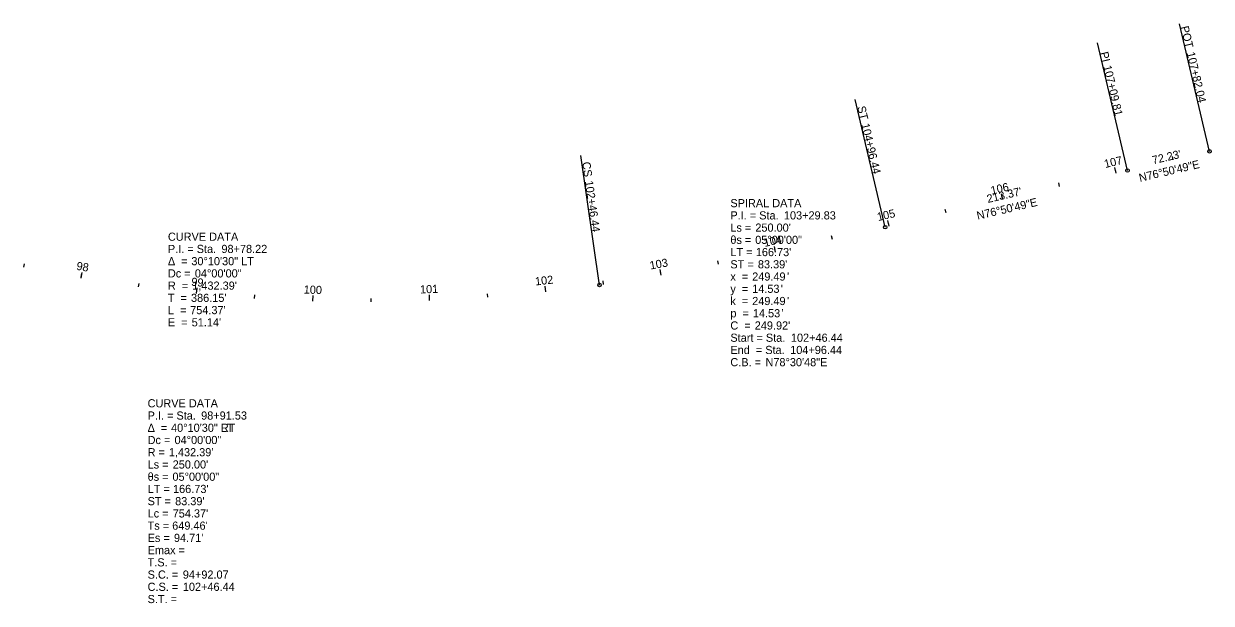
# Model space of a CAD drawing. Extents: x 1999328 to 2003366, y 252318 to 253988.
# Drawn here: x 2002348 to 2003366, y 252507 to 253005 of the extents above; entities that cross this region are included whole.
import ezdxf

# ---------------------------------------------------------------- set-up
doc = ezdxf.new("R2010")
doc.units = 0
for name, color, linetype in [('GE_P_Alignment_500_Stations', 7, 'Continuous'), ('GE_X_Alignment_100_Stations', 7, 'Continuous'), ('SC_Scratch3', 7, 'Continuous'), ('SV_X_Mon_Cells_Found', 7, 'Continuous'), ('TX_P_50', 7, 'Continuous'), ('TX_X_50', 7, 'Continuous')]:
    doc.layers.add(name, color=color, linetype=linetype)

msp = doc.modelspace()

# ---------------------------------------------------------------- linework, layer by layer
at = {"layer": 'GE_P_Alignment_500_Stations'}
for p, q in [((2003364.9, 252895.3), (2003339.3, 253004.9)), ((2003294.6, 252878.9), (2003269, 252988.4)), ((2003086.8, 252830.3), (2003061.2, 252939.9)), ((2002841.9, 252780.6), (2002826, 252891.9)), ((2003333.7, 252888), (2003333.1, 252891)), ((2003285, 252876.7), (2003283.9, 252881.5)), ((2003236.4, 252865.3), (2003235.7, 252868.2)), ((2003187.7, 252853.9), (2003186.5, 252858.8)), ((2003139, 252842.5), (2003138.3, 252845.5)), ((2003090.3, 252831.2), (2003089.2, 252836)), ((2003041.6, 252819.8), (2003040.9, 252822.7)), ((2002992.8, 252808.8), (2002991.8, 252813.7)), ((2002348.2, 252795.9), (2002348.8, 252798.8)), ((2002943.9, 252798.5), (2002943.3, 252801.4)), ((2002397.3, 252786.6), (2002398.2, 252791.5)), ((2002894.8, 252789.1), (2002893.9, 252794)), ((2002446.7, 252779), (2002447.1, 252782)), ((2002496.4, 252773.2), (2002496.9, 252778.2)), ((2002795.9, 252774.7), (2002795.3, 252779.7)), ((2002845.4, 252781.1), (2002845, 252784.1)), ((2002546.2, 252769.1), (2002546.4, 252772.1)), ((2002596.2, 252766.7), (2002596.3, 252771.7)), ((2002646.2, 252766.1), (2002646.2, 252769.1)), ((2002696.2, 252767.3), (2002696, 252772.2)), ((2002746.1, 252770.1), (2002745.8, 252773.1))]:
    msp.add_line(p, q, dxfattribs=at)
for centre in [(2003364.9, 252895.3), (2003294.6, 252878.9), (2003086.8, 252830.3), (2002841.9, 252780.6)]:
    msp.add_circle(centre, 1.5, dxfattribs=at)
at = {"layer": 'SV_X_Mon_Cells_Found'}
for p, q in [((2003364.9, 252895.3), (2003339.3, 253004.9)), ((2003294.6, 252878.9), (2003269, 252988.4)), ((2003086.8, 252830.3), (2003061.2, 252939.9)), ((2002841.9, 252780.6), (2002826, 252891.9)), ((2003090.3, 252831.2), (2003089.6, 252834.1)), ((2002596.2, 252766.7), (2002596.3, 252771.7))]:
    msp.add_line(p, q, dxfattribs=at)
for centre in [(2003364.9, 252895.3), (2003294.6, 252878.9), (2003086.8, 252830.3), (2002841.9, 252780.6)]:
    msp.add_circle(centre, 1.5, dxfattribs=at)
at = {"layer": 'TX_P_50'}
for p, q in [((2003364.9, 252895.3), (2003339.3, 253004.9)), ((2003294.6, 252878.9), (2003269, 252988.4)), ((2003086.8, 252830.3), (2003061.2, 252939.9)), ((2002841.9, 252780.6), (2002826, 252891.9)), ((2003285, 252876.7), (2003284.4, 252879.6)), ((2003187.7, 252853.9), (2003187, 252856.8)), ((2003090.3, 252831.2), (2003089.2, 252836)), ((2002992.8, 252808.8), (2002992.2, 252811.7)), ((2002397.3, 252786.6), (2002397.8, 252789.6)), ((2002894.8, 252789.1), (2002894.3, 252792)), ((2002496.4, 252773.2), (2002496.7, 252776.2)), ((2002596.2, 252766.7), (2002596.3, 252771.7)), ((2002696.2, 252767.3), (2002696, 252770.2)), ((2002795.9, 252774.7), (2002795.5, 252777.7))]:
    msp.add_line(p, q, dxfattribs=at)
for centre in [(2003364.9, 252895.3), (2003294.6, 252878.9), (2003086.8, 252830.3), (2002841.9, 252780.6)]:
    msp.add_circle(centre, 1.5, dxfattribs=at)

# ---------------------------------------------------------------- texts
at = {"layer": 'GE_P_Alignment_500_Stations'}
for s, rotation, p in [('POT', 283.1531, (2003340.1, 253002.1)), ('PI', 283.1531, (2003271.1, 252980)), ('107+82.04', 283.1531, (2003345.3, 252979.9)), ('107+09.81', 283.1531, (2003273.8, 252968.4)), ('ST', 283.1531, (2003062.9, 252933.4)), ('104+96.44', 283.1531, (2003066.3, 252918.6)), ('107', 13.1531, (2003275.5, 252881)), ("72.23'", 13.1531, (2003316.6, 252884.2)), ('CS', 278.1531, (2002827, 252885.9)), ('N76°50\'49"E', 13.1531, (2003305.3, 252869.1)), ('102+46.44', 278.1531, (2002829.3, 252869.7)), ("213.37'", 13.1531, (2003174.9, 252851)), ('106', 13.1531, (2003178.2, 252858.2)), ('N76°50\'49"E', 13.1531, (2003166.2, 252836.6)), ('105', 13.1531, (2003080.8, 252835.5)), ('104', 12.4091, (2002983.6, 252813.3)), ('98', 350.2955, (2002393, 252793.8)), ('103', 10.066, (2002885.6, 252793.9)), ('102', 6.2955, (2002787, 252780.2)), ('99', 354.2955, (2002491.6, 252780.1)), ('100', 358.2955, (2002588.2, 252773.3)), ('101', 2.2955, (2002688.1, 252773.3))]:
    msp.add_text(s, height=7, rotation=rotation, dxfattribs=at).set_placement(p)
at = {"layer": 'GE_X_Alignment_100_Stations'}
for s, p in [('SPIRAL DATA', (2002954.1, 252847.4)), ('P.I. = Sta. ', (2002954.1, 252836.9)), ('103+29.83', (2003000, 252836.9)), ('Ls = ', (2002954.1, 252826.4)), ("250.00'", (2002975.5, 252826.4)), ('CURVE DATA', (2002471.8, 252818.6)), ('θs = ', (2002954.1, 252815.9)), ('05°00\'00"', (2002975.4, 252815.9)), ('P.I. = Sta. ', (2002471.8, 252808.1)), ('98+78.22', (2002517.7, 252808.1)), ('LT = ', (2002954.1, 252805.4)), ("166.73'", (2002975.9, 252805.4)), ('Δ  = ', (2002471.8, 252797.6)), ('30°10\'30" LT', (2002491.9, 252797.6)), ('ST = ', (2002954.1, 252794.9)), ("83.39'", (2002977.7, 252794.9)), ('Dc = ', (2002471.8, 252787.1)), ('04°00\'00"', (2002494.9, 252787.1)), ('x  = ', (2002954.1, 252784.4)), ('249.49', (2002972.8, 252784.4)), ("'", (2003002.7, 252784.4)), ('R  = ', (2002471.8, 252776.6)), ("1,432.39'", (2002492.7, 252776.6)), ('y  = ', (2002954.1, 252773.9)), ('14.53', (2002972.8, 252773.9)), ("'", (2002997.3, 252773.9)), ('T  = ', (2002471.8, 252766.1)), ("386.15'", (2002491.6, 252766.1)), ('k  = ', (2002954.1, 252763.4)), ('249.49', (2002972.8, 252763.4)), ("'", (2003002.7, 252763.4)), ('L  = ', (2002471.8, 252755.6)), ("754.37'", (2002490.9, 252755.6)), ('p  = ', (2002954.1, 252752.9)), ('14.53', (2002973.4, 252752.9)), ("'", (2002997.8, 252752.9)), ('E  = ', (2002471.8, 252745.1)), ("51.14'", (2002492.2, 252745.1)), ('C  = ', (2002954.1, 252742.4)), ("249.92'", (2002975, 252742.4)), ('Start = Sta. ', (2002954.1, 252731.9)), ('102+46.44', (2003006, 252731.9)), ('End  = Sta. ', (2002954.1, 252721.4)), ('104+96.44', (2003005.4, 252721.4)), ('C.B. = ', (2002954.1, 252710.9)), ('N78°30\'48"E', (2002984.2, 252710.9)), ('CURVE DATA', (2002454.4, 252675.6)), ('CURVE DATA', (2002454.4, 252675.6)), ('P.I. = Sta. ', (2002454.4, 252665.1)), ('P.I. = Sta. ', (2002454.4, 252665.1)), ('98+91.53', (2002500.3, 252665.1)), ('98+91.53', (2002500.3, 252665.1)), ('Δ  = ', (2002454.4, 252654.6)), ('Δ  = ', (2002454.4, 252654.6)), ('40°10\'30" LT', (2002474.5, 252654.6)), ('40°10\'30" RT', (2002474.5, 252654.6)), ('Dc = ', (2002454.4, 252644.1)), ('Dc = ', (2002454.4, 252644.1)), ('04°00\'00"', (2002477.5, 252644.1)), ('04°00\'00"', (2002477.5, 252644.1)), ('R = ', (2002454.4, 252633.6)), ('R = ', (2002454.4, 252633.6)), ("1,432.39'", (2002472.6, 252633.6)), ("1,432.39'", (2002472.6, 252633.6)), ('Ls = ', (2002454.4, 252623.1)), ('Ls = ', (2002454.4, 252623.1)), ("250.00'", (2002475.9, 252623.1)), ("250.00'", (2002475.9, 252623.1)), ('θs = ', (2002454.4, 252612.6)), ('θs = ', (2002454.4, 252612.6)), ('05°00\'00"', (2002475.7, 252612.6)), ('05°00\'00"', (2002475.7, 252612.6)), ('LT = ', (2002454.4, 252602.1)), ('LT = ', (2002454.4, 252602.1)), ("166.73'", (2002476.2, 252602.1)), ("166.73'", (2002476.2, 252602.1)), ('ST = ', (2002454.4, 252591.6)), ('ST = ', (2002454.4, 252591.6)), ("83.39'", (2002478, 252591.6)), ("83.39'", (2002478, 252591.6)), ('Lc = ', (2002454.4, 252581.1)), ('Lc = ', (2002454.4, 252581.1)), ("754.37'", (2002475.9, 252581.1)), ("754.37'", (2002475.9, 252581.1)), ('Ts = ', (2002454.4, 252570.6)), ('Ts = ', (2002454.4, 252570.6)), ("649.46'", (2002475.5, 252570.6)), ("649.46'", (2002475.5, 252570.6)), ('Es = ', (2002454.4, 252560.1)), ('Es = ', (2002454.4, 252560.1)), ("94.71'", (2002477, 252560.1)), ("94.71'", (2002477, 252560.1)), ('Emax = ', (2002454.4, 252549.6)), ('Emax = ', (2002454.4, 252549.6)), ('T.S. = ', (2002454.4, 252539.1)), ('T.S. = ', (2002454.4, 252539.1)), ('S.C. = ', (2002454.4, 252528.6)), ('S.C. = ', (2002454.4, 252528.6)), ('94+92.07', (2002484.6, 252528.6)), ('94+92.07', (2002484.6, 252528.6)), ('C.S. = ', (2002454.4, 252518.1)), ('C.S. = ', (2002454.4, 252518.1)), ('102+46.44', (2002484.6, 252518.1)), ('102+46.44', (2002484.6, 252518.1)), ('S.T. = ', (2002454.4, 252507.6)), ('S.T. = ', (2002454.4, 252507.6))]:
    msp.add_text(s, height=7, dxfattribs=at).set_placement(p)
at = {"layer": 'SC_Scratch3'}
for s, p in [('SPIRAL DATA', (2002954.1, 252847.4)), ('P.I. = Sta. ', (2002954.1, 252836.9)), ('103+29.83', (2003000, 252836.9)), ('Ls = ', (2002954.1, 252826.4)), ("250.00'", (2002975.5, 252826.4)), ('CURVE DATA', (2002471.8, 252818.6)), ('θs = ', (2002954.1, 252815.9)), ('05°00\'00"', (2002975.4, 252815.9)), ('P.I. = Sta. ', (2002471.8, 252808.1)), ('98+78.22', (2002517.7, 252808.1)), ('LT = ', (2002954.1, 252805.4)), ("166.73'", (2002975.9, 252805.4)), ('Δ  = ', (2002471.8, 252797.6)), ('30°10\'30" LT', (2002491.9, 252797.6)), ('ST = ', (2002954.1, 252794.9)), ("83.39'", (2002977.7, 252794.9)), ('Dc = ', (2002471.8, 252787.1)), ('04°00\'00"', (2002494.9, 252787.1)), ('x  = ', (2002954.1, 252784.4)), ('249.49', (2002972.8, 252784.4)), ("'", (2003002.7, 252784.4)), ('R  = ', (2002471.8, 252776.6)), ("1,432.39'", (2002492.7, 252776.6)), ('y  = ', (2002954.1, 252773.9)), ('14.53', (2002972.8, 252773.9)), ("'", (2002997.3, 252773.9)), ('T  = ', (2002471.8, 252766.1)), ("386.15'", (2002491.6, 252766.1)), ('k  = ', (2002954.1, 252763.4)), ('249.49', (2002972.8, 252763.4)), ("'", (2003002.7, 252763.4)), ('L  = ', (2002471.8, 252755.6)), ("754.37'", (2002490.9, 252755.6)), ('p  = ', (2002954.1, 252752.9)), ('14.53', (2002973.4, 252752.9)), ("'", (2002997.8, 252752.9)), ('E  = ', (2002471.8, 252745.1)), ("51.14'", (2002492.2, 252745.1)), ('C  = ', (2002954.1, 252742.4)), ("249.92'", (2002975, 252742.4)), ('Start = Sta. ', (2002954.1, 252731.9)), ('102+46.44', (2003006, 252731.9)), ('End  = Sta. ', (2002954.1, 252721.4)), ('104+96.44', (2003005.4, 252721.4)), ('C.B. = ', (2002954.1, 252710.9)), ('N78°30\'48"E', (2002984.2, 252710.9)), ('CURVE DATA', (2002454.4, 252675.6)), ('CURVE DATA', (2002454.4, 252675.6)), ('P.I. = Sta. ', (2002454.4, 252665.1)), ('P.I. = Sta. ', (2002454.4, 252665.1)), ('98+91.53', (2002500.3, 252665.1)), ('98+91.53', (2002500.3, 252665.1)), ('Δ  = ', (2002454.4, 252654.6)), ('Δ  = ', (2002454.4, 252654.6)), ('40°10\'30" LT', (2002474.5, 252654.6)), ('40°10\'30" RT', (2002474.5, 252654.6)), ('Dc = ', (2002454.4, 252644.1)), ('Dc = ', (2002454.4, 252644.1)), ('04°00\'00"', (2002477.5, 252644.1)), ('04°00\'00"', (2002477.5, 252644.1)), ('R = ', (2002454.4, 252633.6)), ('R = ', (2002454.4, 252633.6)), ("1,432.39'", (2002472.6, 252633.6)), ("1,432.39'", (2002472.6, 252633.6)), ('Ls = ', (2002454.4, 252623.1)), ('Ls = ', (2002454.4, 252623.1)), ("250.00'", (2002475.9, 252623.1)), ("250.00'", (2002475.9, 252623.1)), ('θs = ', (2002454.4, 252612.6)), ('θs = ', (2002454.4, 252612.6)), ('05°00\'00"', (2002475.7, 252612.6)), ('05°00\'00"', (2002475.7, 252612.6)), ('LT = ', (2002454.4, 252602.1)), ('LT = ', (2002454.4, 252602.1)), ("166.73'", (2002476.2, 252602.1)), ("166.73'", (2002476.2, 252602.1)), ('ST = ', (2002454.4, 252591.6)), ('ST = ', (2002454.4, 252591.6)), ("83.39'", (2002478, 252591.6)), ("83.39'", (2002478, 252591.6)), ('Lc = ', (2002454.4, 252581.1)), ('Lc = ', (2002454.4, 252581.1)), ("754.37'", (2002475.9, 252581.1)), ("754.37'", (2002475.9, 252581.1)), ('Ts = ', (2002454.4, 252570.6)), ('Ts = ', (2002454.4, 252570.6)), ("649.46'", (2002475.5, 252570.6)), ("649.46'", (2002475.5, 252570.6)), ('Es = ', (2002454.4, 252560.1)), ('Es = ', (2002454.4, 252560.1)), ("94.71'", (2002477, 252560.1)), ("94.71'", (2002477, 252560.1)), ('Emax = ', (2002454.4, 252549.6)), ('Emax = ', (2002454.4, 252549.6)), ('T.S. = ', (2002454.4, 252539.1)), ('T.S. = ', (2002454.4, 252539.1)), ('S.C. = ', (2002454.4, 252528.6)), ('S.C. = ', (2002454.4, 252528.6)), ('94+92.07', (2002484.6, 252528.6)), ('94+92.07', (2002484.6, 252528.6)), ('C.S. = ', (2002454.4, 252518.1)), ('C.S. = ', (2002454.4, 252518.1)), ('102+46.44', (2002484.6, 252518.1)), ('102+46.44', (2002484.6, 252518.1)), ('S.T. = ', (2002454.4, 252507.6)), ('S.T. = ', (2002454.4, 252507.6))]:
    msp.add_text(s, height=7, dxfattribs=at).set_placement(p)
at = {"layer": 'SV_X_Mon_Cells_Found'}
for s, rotation, p in [('POT', 283.1531, (2003340.1, 253002.1)), ('PI', 283.1531, (2003271.1, 252980)), ('107+82.04', 283.1531, (2003345.3, 252979.9)), ('107+09.81', 283.1531, (2003273.8, 252968.4)), ('ST', 283.1531, (2003062.9, 252933.4)), ('104+96.44', 283.1531, (2003066.3, 252918.6)), ("72.23'", 13.1531, (2003316.6, 252884.2)), ('CS', 278.1531, (2002827, 252885.9)), ('N76°50\'49"E', 13.1531, (2003305.3, 252869.1)), ('102+46.44', 278.1531, (2002829.3, 252869.7)), ("213.37'", 13.1531, (2003174.9, 252851)), ('N76°50\'49"E', 13.1531, (2003166.2, 252836.6)), ('100', 358.2955, (2002588.2, 252773.3))]:
    msp.add_text(s, height=7, rotation=rotation, dxfattribs=at).set_placement(p)
at = {"layer": 'TX_P_50'}
for s, rotation, p in [('POT', 283.1531, (2003340.1, 253002.1)), ('PI', 283.1531, (2003271.1, 252980)), ('107+82.04', 283.1531, (2003345.3, 252979.9)), ('107+09.81', 283.1531, (2003273.8, 252968.4)), ('ST', 283.1531, (2003062.9, 252933.4)), ('104+96.44', 283.1531, (2003066.3, 252918.6)), ("72.23'", 13.1531, (2003316.6, 252884.2)), ('CS', 278.1531, (2002827, 252885.9)), ('N76°50\'49"E', 13.1531, (2003305.3, 252869.1)), ('102+46.44', 278.1531, (2002829.3, 252869.7)), ("213.37'", 13.1531, (2003174.9, 252851)), ('N76°50\'49"E', 13.1531, (2003166.2, 252836.6)), ('105', 13.1531, (2003080.8, 252835.5)), ('100', 358.2955, (2002588.2, 252773.3))]:
    msp.add_text(s, height=7, rotation=rotation, dxfattribs=at).set_placement(p)
at = {"layer": 'TX_X_50'}
for s, p in [('SPIRAL DATA', (2002954.1, 252847.4)), ('P.I. = Sta. ', (2002954.1, 252836.9)), ('103+29.83', (2003000, 252836.9)), ('Ls = ', (2002954.1, 252826.4)), ("250.00'", (2002975.5, 252826.4)), ('CURVE DATA', (2002471.8, 252818.6)), ('θs = ', (2002954.1, 252815.9)), ('05°00\'00"', (2002975.4, 252815.9)), ('P.I. = Sta. ', (2002471.8, 252808.1)), ('98+78.22', (2002517.7, 252808.1)), ('LT = ', (2002954.1, 252805.4)), ("166.73'", (2002975.9, 252805.4)), ('Δ  = ', (2002471.8, 252797.6)), ('30°10\'30" LT', (2002491.9, 252797.6)), ('ST = ', (2002954.1, 252794.9)), ("83.39'", (2002977.7, 252794.9)), ('Dc = ', (2002471.8, 252787.1)), ('04°00\'00"', (2002494.9, 252787.1)), ('x  = ', (2002954.1, 252784.4)), ('249.49', (2002972.8, 252784.4)), ("'", (2003002.7, 252784.4)), ('R  = ', (2002471.8, 252776.6)), ("1,432.39'", (2002492.7, 252776.6)), ('y  = ', (2002954.1, 252773.9)), ('14.53', (2002972.8, 252773.9)), ("'", (2002997.3, 252773.9)), ('T  = ', (2002471.8, 252766.1)), ("386.15'", (2002491.6, 252766.1)), ('k  = ', (2002954.1, 252763.4)), ('249.49', (2002972.8, 252763.4)), ("'", (2003002.7, 252763.4)), ('L  = ', (2002471.8, 252755.6)), ("754.37'", (2002490.9, 252755.6)), ('p  = ', (2002954.1, 252752.9)), ('14.53', (2002973.4, 252752.9)), ("'", (2002997.8, 252752.9)), ('E  = ', (2002471.8, 252745.1)), ("51.14'", (2002492.2, 252745.1)), ('C  = ', (2002954.1, 252742.4)), ("249.92'", (2002975, 252742.4)), ('Start = Sta. ', (2002954.1, 252731.9)), ('102+46.44', (2003006, 252731.9)), ('End  = Sta. ', (2002954.1, 252721.4)), ('104+96.44', (2003005.4, 252721.4)), ('C.B. = ', (2002954.1, 252710.9)), ('N78°30\'48"E', (2002984.2, 252710.9)), ('CURVE DATA', (2002454.4, 252675.6)), ('P.I. = Sta. ', (2002454.4, 252665.1)), ('98+91.53', (2002500.3, 252665.1)), ('Δ  = ', (2002454.4, 252654.6)), ('40°10\'30" LT', (2002474.5, 252654.6)), ('Dc = ', (2002454.4, 252644.1)), ('04°00\'00"', (2002477.5, 252644.1)), ('R = ', (2002454.4, 252633.6)), ("1,432.39'", (2002472.6, 252633.6)), ('Ls = ', (2002454.4, 252623.1)), ("250.00'", (2002475.9, 252623.1)), ('θs = ', (2002454.4, 252612.6)), ('05°00\'00"', (2002475.7, 252612.6)), ('LT = ', (2002454.4, 252602.1)), ("166.73'", (2002476.2, 252602.1)), ('ST = ', (2002454.4, 252591.6)), ("83.39'", (2002478, 252591.6)), ('Lc = ', (2002454.4, 252581.1)), ("754.37'", (2002475.9, 252581.1)), ('Ts = ', (2002454.4, 252570.6)), ("649.46'", (2002475.5, 252570.6)), ('Es = ', (2002454.4, 252560.1)), ("94.71'", (2002477, 252560.1)), ('Emax = ', (2002454.4, 252549.6)), ('T.S. = ', (2002454.4, 252539.1)), ('S.C. = ', (2002454.4, 252528.6)), ('94+92.07', (2002484.6, 252528.6)), ('C.S. = ', (2002454.4, 252518.1)), ('102+46.44', (2002484.6, 252518.1)), ('S.T. = ', (2002454.4, 252507.6))]:
    msp.add_text(s, height=7, dxfattribs=at).set_placement(p)

doc.saveas('drawing.dxf')
